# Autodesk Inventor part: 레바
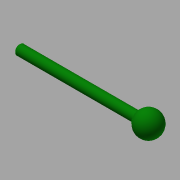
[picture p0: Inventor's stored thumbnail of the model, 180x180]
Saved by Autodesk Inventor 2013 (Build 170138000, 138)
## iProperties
Created: 2015-12
Part Number: 레바
Material: 스테인리스강
Document SubType Name: Modeling
Designer: mduedu
Density: 8.08 g/cm^3
Mass: 30.7693 g
Surface Area: 20.8622 cm^2
Volume: 3.80808 cm^3
Author: mduedu
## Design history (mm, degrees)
sketch "스케치1"
  geometry: C1 r 3 at (0, 0); 1 further point
  constraints: 1 centre point, 1 coincident
  dimensions: "d0" = 6 diameter of C1
extrude "돌출1" new body sketch "스케치1" distance "d1" = 80; taper "d2" = 0 deg
sketch "스케치2"
  geometry: L1 (7.5, 0)-(-6, 0); L2 (-6, 4.5)-(-6, 0); A1 r 7.5 centre (0, 0) between (7.5, 0) and (-6, 4.5); 2 further points
  constraints: 4 end point, 2 coincident, 2 point on circle, 1 centre point, 1 horizontal, 1 perpendicular, 1 point on line
  dimensions: "d3" = 15 diameter of A1; "d10" = 6 distance from line of L2 point (0, 0)
revolve "회전1" sketch "스케치2" stored, may be unused: angle "d4" = 90 deg
chamfer "모따기1" distance "d7" = 0.5; stored, may be unused: second distance "d8" = 2, angle "d9" = 45 deg
fillet "모깎기2" dims "d11" = 0.3
node "솔리드1"
